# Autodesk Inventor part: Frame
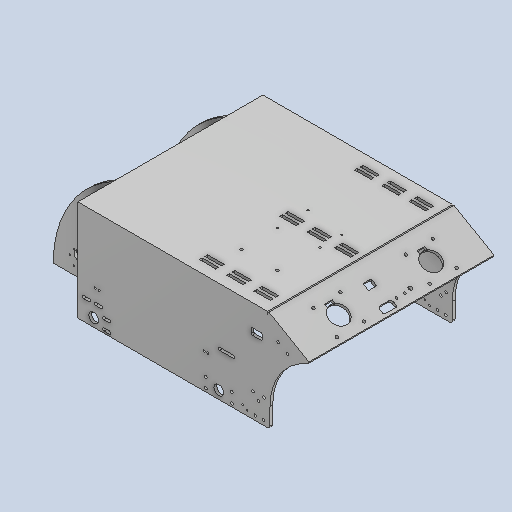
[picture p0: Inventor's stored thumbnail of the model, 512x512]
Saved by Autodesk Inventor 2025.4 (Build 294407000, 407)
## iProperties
Created: 2026-06
Part Number: Frame
Material: Generic
Document SubType Name: Modeling
Designer: AdminForWorker
Density: 1 g/cm^3
Appearance: Default
Title: Frame
Author: AdminForWorker
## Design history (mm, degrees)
feature "Frame"
body "Solid1"
